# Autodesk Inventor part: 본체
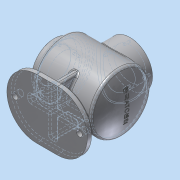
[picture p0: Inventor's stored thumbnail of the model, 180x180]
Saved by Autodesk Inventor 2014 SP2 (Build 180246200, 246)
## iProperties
Created: 2016-04
Part Number: 본체
Material: 알루미늄 6061
Document SubType Name: Modeling
Designer: SCD-A19
Density: 2.71 g/cm^3
Appearance: 알루미늄 - 평지
Mass: 909.903 g
Surface Area: 1227.61 cm^2
Volume: 335.757 cm^3
Author: SCD-A19
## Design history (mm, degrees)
sketch "스케치1"
  geometry: L1 (-55, 0)-(55, 0); L2 (-55, 0)-(-55, 50); L3 (-55, 50)-(44.087, 50); L4 (42.145, 47)-(-52, 47); L5 (-52, 47)-(-52, 0); L6 (-55, 0)-(55, 0); A1 r 120 centre (-65, 0) between (55, 0) and (44.087, 50); A2 r 117 centre (-65, 0) between (52, 0) and (42.145, 47); 2 further points
  constraints: 12 end point, 4 perpendicular, 4 point on circle, 2 centre point, 2 point on line, 1 coincident, 1 horizontal, 1 midpoint
  dimensions: "d1" = 100 diameter of L3 L1; "d64" = 110 distance from line of L1.end L2
revolve "회전1" stored, may be unused: angle "d2" = 90 deg
sketch "스케치2"
  geometry: C1 r 50 at (0, 0) reference; C2 r 38 at (0, 0)
  constraints: 1 centre point, 1 coincident
  dimensions: "d3" = 76 diameter of C2
extrude "돌출1" join sketch "스케치2" distance "d4" = 12; taper "d5" = 0 deg
node "작업 평면3"
sketch "스케치3"
  geometry: C1 r 38 at (5, 0); 1 further point
  constraints: 1 centre point
  dimensions: "d106" = 76 diameter of C1
extrude "돌출2" join sketch "스케치3" stored distance "d8" = 12; taper "d9" = 0 deg
sketch "스케치4"
  geometry: C1 r 38 at (-5, 0) reference; C2 r 27 at (-5, 0)
  constraints: 1 centre point, 1 coincident
  dimensions: "d107" = 54 diameter of C2
sketch "스케치5"
  geometry: C1 r 38 at (0, 0) reference; C2 r 27 at (0, 0)
  constraints: 1 centre point, 1 coincident
  dimensions: "d11" = 54 diameter of C2
extrude "돌출3" cut sketch "스케치5" distance "d12" = 15; taper "d13" = 0 deg
revolve "회전2" stored, may be unused: angle "d21" = 90 deg
fillet "모깎기1" dims "d24" = 2
sketch "스케치10" dims "d36" = 65
  geometry: C1 r 38 at (0, 0) reference; 2 further points
  constraints: 1 coincident, 1 vertical alignment, 2 other
hole "구멍2" sketch "스케치10" at (0, 32.5) diameter "d37" = 3.242; stored, may be unused: countersink angle "d41" = 90 deg, drill point angle "d43" = 118 deg; dims "d38" = 8, "d39" = 4, "d40" = 2, "d42" = 10
fillet "모깎기2" dims "d47" = 5
chamfer "모따기1" distance "d48" = 1; stored, may be unused: second distance "d49" = 2, angle "d50" = 45 deg
fillet "모깎기3" dims "d51" = 3
sketch "스케치13"
  geometry: L1 (-79, -50)-(-79, 50); L2 (0, 0)-(-69, 0); L3 (-69, -50)-(-69, 50); L4 (-69, 50)-(-79, 50); L5 (-69, -50)-(-79, -50); 1 further point
  constraints: 10 end point, 2 perpendicular, 1 horizontal alignment
  dimensions: "d60" = 69 distance of L2.start L2.end; "d61" = 100 distance of L3.start L3.end
extrude "돌출6" join sketch "스케치13" stored distance "d62" = 135; taper "d63" = 0 deg
sketch "스케치15"
  geometry: L1 (-69, -50)-(-69, 50) reference; L2 (-69, -40)-(-30, -40); L3 (0, 0)-(-69, 0); L4 (-69, 40)-(-30, 40); L5 (-69, -40)-(-69, 40); A1 r 50 centre (0, 0) between (50, 0) and (50, 0) reference; A2 r 50 centre (0, 0) between (-30, 40) and (-30, -40); 1 further point
  constraints: 8 end point, 3 point on circle, 2 symmetric about line, 1 centre point, 1 coincident, 1 collinear, 1 midpoint, 1 perpendicular, 1 point on line
extrude "돌출8" join sketch "스케치15" stored distance "d70" = 10; taper "d71" = 0 deg
sketch "스케치16"
  geometry: L1 (-50, -50)-(40.83, -50) reference; L2 (67.5, -69)-(-67.5, -69) reference; L3 (-36.65, -50)-(-40, -69); L4 (36.65, -50)-(40, -69); 1 further point
  constraints: 4 end point, 2 point on line
  dimensions: "d72" = 100 deg angle of L2 L3; "d73" = 40 horizontal distance of point (0, 0) L3.end
feature "리브1" dims "d74" = 1, "d75" = 10, "d76" = 0, "d77" = 0, "d78" = 1, "d79" = 1
feature "리브2" dims "d80" = 1, "d81" = 10, "d82" = 0, "d83" = 0, "d84" = 1, "d85" = 1
fillet "모깎기7" dims "d91" = 50
chamfer "모따기3" distance "d92" = 3; stored, may be unused: second distance "d93" = 2, angle "d94" = 45 deg
sketch "스케치17"
  geometry: L1 (35, 0)-(0, 0) reference; L2 (0, 94)-(35, 94) reference; L3 (17.5, 47)-(17.5, 66.457); L4 (12.5, 42)-(-22.5, 42) reference; L5 (-22.5, 42)-(-22.5, 52) reference; L6 (-22.5, 52)-(12.5, 52) reference; L7 (12.5, 52)-(12.5, 87) reference; L8 (12.5, 87)-(22.5, 87) reference; L9 (22.5, 87)-(22.5, 52) reference; L10 (22.5, 52)-(57.5, 52) reference; L11 (57.5, 52)-(57.5, 42) reference; L12 (57.5, 42)-(22.5, 42) reference; L13 (22.5, 42)-(22.5, 7) reference; L14 (22.5, 7)-(12.5, 7) reference; L15 (12.5, 7)-(12.5, 42) reference; C1 r 5 at (71.5, 47); A1 r 47 centre (0, 47) between (0, 94) and (0, 0) reference; A2 r 47 centre (35, 47) between (35, 0) and (35, 94) reference
  constraints: 2 end point, 1 centre point
  dimensions: "d95" = 10 diameter of C1; "d96" = 54 distance of C1.centre L3.start
extrude "돌출9" cut sketch "스케치17" stored distance "d97" = 10; taper "d98" = 0 deg
node "작업 평면7"
sketch "스케치18"
  geometry: 2 further points
  constraints: 1 coincident, 1 other
feature "엠보싱1" sketch "스케치18" dims "d1" = 100, "d64" = 110, "d100" = 0.5, "d101" = 0
extrude "돌출10" cut sketch "스케치4" stored distance "d108" = 10; taper "d109" = 0 deg
sketch "스케치19"
  geometry: 2 further points
hole "구멍3" sketch "스케치19" at (-32.5, 0) diameter "d111" = 3.242; stored, may be unused: countersink angle "d115" = 90 deg, drill point angle "d117" = 118 deg; dims "d112" = 8, "d113" = 4, "d114" = 2, "d116" = 10
fillet "모깎기8" dims "d121" = 3
fillet "모깎기9" dims "d122" = 3
fillet "모깎기10" dims "d123" = 3
node "솔리드1"
pattern_circular "원형 패턴2" dims angle "d45" = 360 deg
mirror "대칭1"
pattern_circular "원형 패턴3" dims angle "d119" = 360 deg
node "절단 모서리 투영1"
other parameters: "d6" = 65, "d99" = 63.5
